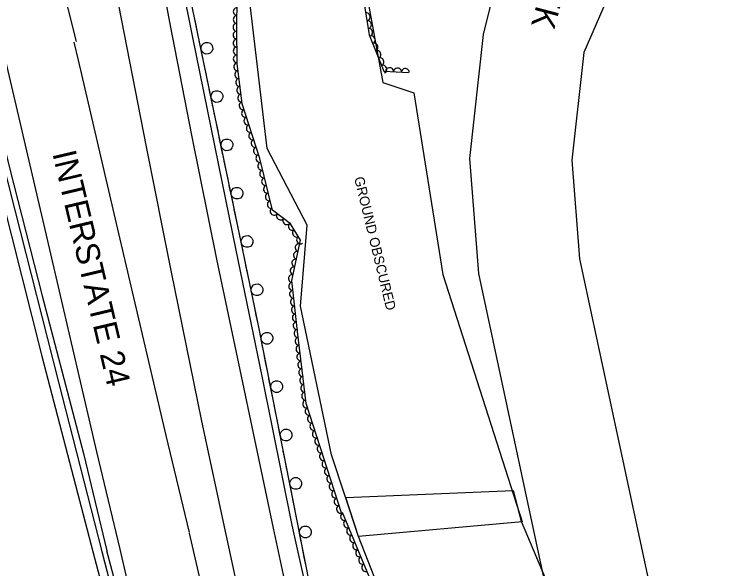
# Model space of a CAD drawing. Extents: x 1746719 to 1766531, y 631721 to 662391.
# Drawn here: x 1753932 to 1754288.6, y 651183.8 to 651464.9 of the extents above; entities that cross this region are included whole.
import ezdxf

# ---------------------------------------------------------------- set-up
doc = ezdxf.new("R2010")
doc.units = 0
for name, color, linetype in [('SURVEY - AERIAL SURVEY - Photo Control - Points - Elevations', 7, 'Continuous'), ('SURVEY - AERIAL SURVEY - Photo Control - Points - Locators', 7, 'Continuous'), ('SURVEY - AERIAL SURVEY - Photo Control - Points - Numbers', 7, 'Continuous'), ('SURVEY - AERIAL SURVEY - Photo Control with Text', 7, 'Continuous'), ('SURVEY - CONTROL - Points - Locators', 7, 'Continuous'), ('SURVEY - CONTROL - Points - Numbers', 7, 'Continuous')]:
    doc.layers.add(name, color=color, linetype=linetype)

msp = doc.modelspace()

# ---------------------------------------------------------------- linework, layer by layer
at = {"layer": 'SURVEY - AERIAL SURVEY - Photo Control - Points - Elevations'}
for points in [[(1753936.87, 651926.35), (1753944.6, 651865.12), (1753950.74, 651820.59), (1753957.41, 651772.23), (1753965.23, 651721.18), (1753973.44, 651670.2), (1753981.5, 651621.64), (1753988.03, 651583.18), (1753998.9, 651523.78), (1754010.93, 651459.97), (1754022.05, 651402.76), (1754034.51, 651340.74), (1754048.44, 651275.01), (1754063.35, 651204.56)], [(1753944.83, 651928.95), (1753952.21, 651883.69), (1753958.42, 651840.35), (1753965.12, 651789.61), (1753976.49, 651712.42), (1753982.86, 651673.43), (1753989.3, 651630.05), (1753999.61, 651567.77), (1754012.04, 651504.42), (1754022.28, 651453.88), (1754033.75, 651397.52), (1754044.29, 651345.29), (1754057.61, 651281.43), (1754072.82, 651206.04)], [(1753913.44, 651918.14), (1753925.09, 651828.85), (1753936.36, 651748.79), (1753952.06, 651651.73), (1753970.61, 651545.77), (1753983.61, 651476.45), (1753998.92, 651397.63), (1754011.4, 651335.08), (1754026.94, 651258.76), (1754039.38, 651201.31)], [(1753963.71, 651451.07), (1753955.57, 651483.26), (1753935.59, 651563.21), (1753913.95, 651648.97), (1753895.33, 651722.66), (1753876.69, 651798.75), (1753852.09, 651899.89)], [(1753816.84, 651890.61), (1753830.85, 651831.07), (1753849.61, 651754.68), (1753866.95, 651686.19), (1753887.01, 651606.61), (1753909.25, 651518.98), (1753929.48, 651433.33), (1753948.74, 651350.66), (1753973.86, 651243.1), (1753985.66, 651193.84)], [(1753794.98, 651884.53), (1753806.82, 651840.15), (1753821.01, 651784.89), (1753834.83, 651732.27), (1753860.34, 651631.97), (1753880.16, 651554.64), (1753901.48, 651468.39), (1753925.64, 651372.59), (1753946.08, 651291.56), (1753972.17, 651192.06)], [(1753962.36, 651450.73), (1753964.53, 651441.55), (1753983.8, 651358.83), (1754008.89, 651251.38), (1754020.67, 651202.22)], [(1754072.82, 651206.04), (1754094.18, 651109.83), (1754112.14, 651031.33), (1754123.49, 650982.98), (1754145.46, 650887.82), (1754164.53, 650808.3), (1754187.99, 650714.26), (1754218.11, 650592.11), (1754265.98, 650448.02)], [(1754063.35, 651204.56), (1754079.53, 651128.87), (1754096.68, 651054.56), (1754113.23, 650983.52), (1754128.08, 650921.41), (1754151.45, 650825.16), (1754182.39, 650697.84)], [(1754020.74, 651201.91), (1754034.03, 651144.22), (1754049.15, 651082.15), (1754058.18, 651048.02), (1754078.02, 650978.02), (1754103.01, 650889.26), (1754131.48, 650789.68), (1754151.45, 650719.85)], [(1754039.38, 651201.31), (1754051.19, 651146.66), (1754067.85, 651073.3), (1754085.71, 650996.02), (1754102.41, 650922.67), (1754117.55, 650859.55), (1754134.13, 650790.75), (1754151.45, 650719.85)], [(1753972.17, 651192.06), (1753992.25, 651116.01), (1754015.21, 651030.74), (1754038.02, 650948.81), (1754060.55, 650869.78), (1754089.76, 650767.41), (1754112.32, 650689.17), (1754146.8, 650566.94), (1754158.11, 650527.42), (1754160.85, 650517.83)], [(1753985.66, 651193.84), (1753999, 651135.92), (1754014.26, 651073.28), (1754023.46, 651038.51), (1754043.38, 650968.24), (1754068.37, 650879.43), (1754096.87, 650779.78), (1754126.64, 650675.65), (1754149.99, 650593.47), (1754178.2, 650495.46), (1754179.47, 650490.6)]]:
    msp.add_lwpolyline(points, dxfattribs=at)
at = {"layer": 'SURVEY - AERIAL SURVEY - Photo Control - Points - Locators'}
for points in [[(1754107.03, 651494.65), (1754118.81, 651430.22), (1754134.54, 651425.02), (1754149.25, 651333.04), (1754189.42, 651207.71), (1754106.53, 651200.34)], [(1754106.53, 651200.34), (1754092.9, 651241.67), (1754077.11, 651316.87), (1754080.55, 651357.9), (1754060.26, 651396.75), (1754051.2, 651474.09)], [(1754122.75, 651158.86), (1754106.53, 651200.34), (1754106.53, 651200.34), (1754100.19, 651220.07), (1754184.86, 651223.64), (1754189.03, 651208.12), (1754228.69, 651114.03)]]:
    msp.add_lwpolyline(points, dxfattribs=at)
at = {"layer": 'SURVEY - AERIAL SURVEY - Photo Control - Points - Numbers'}
for points in [[(1753799.94, 651885.56), (1753810.5, 651844.2), (1753821.9, 651799.8), (1753839.06, 651731.78), (1753855.62, 651667.72), (1753872.26, 651603.05), (1753890.45, 651531.05), (1753906.57, 651466.95), (1753932.35, 651365.49), (1753954.46, 651278.36), (1753976.4, 651192.62)], [(1753803.22, 651885.31), (1753820.95, 651816.44), (1753833.87, 651765.85), (1753848.12, 651709.37), (1753866.6, 651636.42), (1753879.49, 651585.73), (1753898.23, 651511.96), (1753915.25, 651443.91), (1753931.92, 651378.33), (1753946.18, 651322.21), (1753967.15, 651242.27), (1753979.08, 651193.03)], [(1754277.22, 650442.59), (1754261.86, 650465.35), (1754221.06, 650591.52), (1754167.3, 650808.68), (1754121.44, 651004.08), (1754085.73, 651156.22), (1754055.64, 651308.03), (1754019.01, 651484.3)], [(1754024.21, 651459.28), (1754023.25, 651463.88)], [(1754025.17, 651454.67), (1754024.21, 651459.28)], [(1754027.69, 651442.53), (1754025.82, 651451.54)], [(1754029.3, 651434.8), (1754028.34, 651439.4)], [(1754030.25, 651430.2), (1754029.3, 651434.8)], [(1754032.78, 651418.06), (1754030.9, 651427.06)], [(1754034.38, 651410.32), (1754033.43, 651414.92)], [(1754035.34, 651405.72), (1754034.38, 651410.32)], [(1754037.86, 651393.58), (1754035.99, 651402.59)], [(1754039.47, 651385.84), (1754038.51, 651390.45)], [(1754040.43, 651381.24), (1754039.47, 651385.84)], [(1754042.95, 651369.1), (1754041.08, 651378.11)], [(1754044.56, 651361.37), (1754043.6, 651365.97)], [(1754045.51, 651356.77), (1754044.56, 651361.37)], [(1754048.04, 651344.62), (1754046.16, 651353.63)], [(1754049.64, 651336.89), (1754048.69, 651341.49)], [(1754050.6, 651332.29), (1754049.64, 651336.89)], [(1754053.12, 651320.15), (1754051.25, 651329.16)], [(1754054.73, 651312.41), (1754053.77, 651317.01)], [(1754055.69, 651307.81), (1754055.64, 651308.03), (1754054.73, 651312.41)], [(1754058.1, 651295.65), (1754056.31, 651304.67)], [(1754059.63, 651287.9), (1754058.72, 651292.51)], [(1754060.55, 651283.29), (1754059.63, 651287.9)], [(1754062.96, 651271.12), (1754061.17, 651280.15)], [(1754064.49, 651263.38), (1754063.58, 651267.98)], [(1754065.41, 651258.77), (1754064.49, 651263.38)], [(1754067.82, 651246.6), (1754066.03, 651255.63)], [(1754069.35, 651238.85), (1754068.44, 651243.46)], [(1754070.27, 651234.24), (1754069.35, 651238.85)], [(1754072.68, 651222.08), (1754070.89, 651231.1)], [(1754074.22, 651214.33), (1754073.3, 651218.94)], [(1754075.13, 651209.72), (1754074.22, 651214.33)], [(1754077.54, 651197.56), (1754075.75, 651206.58)], [(1753976.4, 651192.62), (1753985.63, 651157.37), (1753999.56, 651107.38), (1754017.65, 651041.27), (1754039.67, 650963.99), (1754046.76, 650939.07), (1754050.77, 650921.6), (1754055, 650908.04), (1754059.02, 650896.07), (1754079.37, 650824.52), (1754099.29, 650754.42), (1754120.26, 650679.29), (1754139.53, 650612.32), (1754166.51, 650517.9)], [(1754175.8, 650492.56), (1754160.24, 650546.46), (1754142.04, 650609.69), (1754125.24, 650668.34), (1754110.86, 650720.6), (1754096.24, 650772.39), (1754077.82, 650836.36), (1754059.64, 650900.45), (1754056.28, 650915.36), (1754049.84, 650936.52), (1754045.21, 650951.78), (1754029.02, 651009.31), (1754011.97, 651069.98), (1753996.6, 651127.12), (1753979.08, 651193.03)], [(1754079.08, 651189.81), (1754078.16, 651194.42)], [(1754079.99, 651185.2), (1754079.08, 651189.81)]]:
    msp.add_lwpolyline(points, dxfattribs=at)
for centre, start, end in [((1754029.7, 651447.6), 305.0086, 304.9946), ((1754034.79, 651423.13), 305.0086, 304.9946), ((1754039.87, 651398.65), 305.0086, 304.9946), ((1754044.96, 651374.17), 305.0086, 304.9946), ((1754050.05, 651349.69), 305.0086, 304.9946), ((1754055.13, 651325.22), 305.0086, 304.9946), ((1754060.15, 651300.7), 304.4806, 304.4666), ((1754065.01, 651276.18), 304.4806, 304.4666), ((1754069.87, 651251.65), 304.4806, 304.4666), ((1754074.74, 651227.13), 304.4806, 304.4666), ((1754079.6, 651202.61), 304.4806, 304.4666)]:
    msp.add_arc(centre, 3, start, end, dxfattribs=at)
at = {"layer": 'SURVEY - AERIAL SURVEY - Photo Control with Text'}
for points in [[(1754123.93, 651635.81), (1754115.82, 651605.86), (1754110.63, 651577), (1754119.1, 651558.62), (1754109.82, 651530.12), (1754111.19, 651508.9), (1754112.78, 651492.66), (1754113.58, 651478.66), (1754109.82, 651468.02), (1754111.99, 651454.45), (1754119.32, 651436.02), (1754131.93, 651435.29)], [(1754097.88, 651212.2), (1754080.09, 651267.57), (1754075.68, 651304.12), (1754072.73, 651329.92), (1754077.14, 651350.37), (1754072.11, 651358.68), (1754062.94, 651365.54), (1754056.47, 651391.66), (1754047.65, 651419.45), (1754044.97, 651439.9), (1754044.89, 651457.95), (1754045.24, 651487.87)], [(1754437.51, 650352.91), (1754373.46, 650364.73), (1754342.18, 650371.08), (1754330.7, 650387.52), (1754322.19, 650421.14), (1754324.94, 650470.68), (1754320.13, 650524.69), (1754316.48, 650564.69), (1754305.81, 650600.41), (1754286.82, 650634.23), (1754280.52, 650686.12), (1754274.54, 650724.16), (1754269.28, 650750.14), (1754249.03, 650765.51), (1754227.91, 650772.31), (1754210.67, 650824.74), (1754196.82, 650877.62), (1754188.5, 650922.64), (1754171.01, 650976.43), (1754157.32, 651016.92), (1754145.6, 651062.07), (1754133.69, 651111.97), (1754119.69, 651161.21), (1754098.48, 651212.49)]]:
    msp.add_lwpolyline(points, dxfattribs=at)
for centre, major_axis in [((1754044.98, 651466.18), (0.02, 2)), ((1754044.94, 651462.18), (0.02, 2)), ((1754110.54, 651463.52), (0.32, -1.97)), ((1754044.89, 651458.18), (0.02, 2)), ((1754111.17, 651459.57), (0.32, -1.97)), ((1754044.9, 651454.18), (-0.01, 2)), ((1754111.81, 651455.62), (0.32, -1.97)), ((1754044.92, 651450.18), (-0.01, 2)), ((1754113.03, 651451.83), (0.74, -1.86)), ((1754114.51, 651448.12), (0.74, -1.86)), ((1754044.94, 651446.18), (-0.01, 2)), ((1754115.99, 651444.4), (0.74, -1.86)), ((1754044.96, 651442.18), (-0.01, 2)), ((1754117.47, 651440.68), (0.74, -1.86)), ((1754045.19, 651438.19), (-0.26, 1.98)), ((1754118.95, 651436.97), (0.74, -1.86)), ((1754122.3, 651435.85), (2, -0.12)), ((1754045.71, 651434.23), (-0.26, 1.98)), ((1754126.29, 651435.62), (2, -0.12)), ((1754130.28, 651435.39), (2, -0.12)), ((1754046.23, 651430.26), (-0.26, 1.98)), ((1754046.76, 651426.3), (-0.26, 1.98)), ((1754047.28, 651422.33), (-0.26, 1.98)), ((1754047.98, 651418.41), (-0.6, 1.91)), ((1754049.19, 651414.59), (-0.6, 1.91)), ((1754050.4, 651410.78), (-0.6, 1.91)), ((1754051.61, 651406.97), (-0.6, 1.91)), ((1754052.82, 651403.16), (-0.6, 1.91)), ((1754054.03, 651399.34), (-0.6, 1.91)), ((1754055.24, 651395.53), (-0.6, 1.91)), ((1754056.45, 651391.72), (-0.6, 1.91)), ((1754057.42, 651387.84), (-0.48, 1.94)), ((1754058.38, 651383.95), (-0.48, 1.94)), ((1754059.34, 651380.07), (-0.48, 1.94)), ((1754060.3, 651376.19), (-0.48, 1.94)), ((1754061.26, 651372.31), (-0.48, 1.94)), ((1754062.23, 651368.42), (-0.48, 1.94)), ((1754063.77, 651364.92), (-1.6, 1.2)), ((1754066.97, 651362.53), (-1.6, 1.2)), ((1754070.17, 651360.13), (-1.6, 1.2)), ((1754072.93, 651357.33), (-1.04, 1.71)), ((1754075, 651353.91), (-1.04, 1.71)), ((1754077.07, 651350.49), (-1.04, 1.71)), ((1754076.33, 651346.59), (0.42, 1.95)), ((1754075.48, 651342.68), (0.42, 1.95)), ((1754074.64, 651338.77), (0.42, 1.95)), ((1754073.79, 651334.86), (0.42, 1.95)), ((1754072.95, 651330.95), (0.42, 1.95)), ((1754073.06, 651327), (-0.23, 1.99)), ((1754073.51, 651323.02), (-0.23, 1.99)), ((1754073.97, 651319.05), (-0.23, 1.99)), ((1754074.42, 651315.07), (-0.23, 1.99)), ((1754074.88, 651311.1), (-0.23, 1.99)), ((1754075.33, 651307.12), (-0.23, 1.99)), ((1754075.79, 651303.15), (-0.24, 1.99)), ((1754076.27, 651299.18), (-0.24, 1.99)), ((1754076.75, 651295.21), (-0.24, 1.99)), ((1754077.23, 651291.24), (-0.24, 1.99)), ((1754077.71, 651287.27), (-0.24, 1.99)), ((1754078.19, 651283.3), (-0.24, 1.99)), ((1754078.67, 651279.32), (-0.24, 1.99)), ((1754079.15, 651275.35), (-0.24, 1.99)), ((1754079.63, 651271.38), (-0.24, 1.99)), ((1754080.14, 651267.42), (-0.61, 1.9)), ((1754081.36, 651263.61), (-0.61, 1.9)), ((1754082.58, 651259.8), (-0.61, 1.9)), ((1754083.81, 651255.99), (-0.61, 1.9)), ((1754085.03, 651252.18), (-0.61, 1.9)), ((1754086.25, 651248.38), (-0.61, 1.9)), ((1754087.48, 651244.57), (-0.61, 1.9)), ((1754088.7, 651240.76), (-0.61, 1.9)), ((1754089.93, 651236.95), (-0.61, 1.9)), ((1754091.15, 651233.14), (-0.61, 1.9)), ((1754092.37, 651229.34), (-0.61, 1.9)), ((1754093.6, 651225.53), (-0.61, 1.9)), ((1754094.82, 651221.72), (-0.61, 1.9)), ((1754096.05, 651217.91), (-0.61, 1.9)), ((1754097.27, 651214.1), (-0.61, 1.9)), ((1754099.37, 651210.35), (-0.76, 1.85)), ((1754100.89, 651206.66), (-0.76, 1.85)), ((1754102.42, 651202.96), (-0.76, 1.85)), ((1754103.95, 651199.26), (-0.76, 1.85)), ((1754105.48, 651195.57), (-0.76, 1.85)), ((1754107.01, 651191.87), (-0.76, 1.85)), ((1754108.54, 651188.17), (-0.76, 1.85)), ((1754110.06, 651184.48), (-0.76, 1.85))]:
    msp.add_ellipse(centre, major_axis=major_axis, ratio=0.940188, start_param=0, end_param=3.141593, dxfattribs=at)
at = {"layer": 'SURVEY - CONTROL - Points - Locators'}
for points in [[(1754355.39, 651800.12), (1754279.49, 651732.05), (1754250.7, 651685.75), (1754218.54, 651615.28), (1754190.08, 651536.67), (1754169.64, 651454.54), (1754162.69, 651391.74), (1754167.28, 651333.43), (1754239.48, 650996.5), (1754258.15, 650928.17), (1754277.98, 650866.22), (1754308.69, 650819.4), (1754334.91, 650784.12), (1754384.39, 650741.68), (1754438.42, 650718.28), (1754518.34, 650691.93), (1754607.58, 650664.15), (1754710.2, 650648.48)], [(1754389.89, 651761.65), (1754319.48, 651698.5), (1754296.33, 651661.28), (1754262.05, 651598.43), (1754247.41, 651506.85), (1754220.62, 651445.41), (1754214.59, 651390.92), (1754218.53, 651340.91), (1754289.71, 651008.73), (1754307.7, 650942.87), (1754325.06, 650888.68), (1754351.07, 650849.01), (1754367.14, 650811.09), (1754406.29, 650777.49), (1754456.82, 650766.63), (1754530.29, 650748.7), (1754619.23, 650714.65), (1754717.99, 650699.57)]]:
    msp.add_lwpolyline(points, dxfattribs=at)

# ---------------------------------------------------------------- texts
at = {"layer": 'SURVEY - AERIAL SURVEY - Photo Control - Points - Locators'}
msp.add_text('GROUND OBSCURED', height=5, rotation=283.7394, dxfattribs=at).set_placement((1754104.27, 651381.86))
at = {"layer": 'SURVEY - CONTROL - Points - Numbers'}
for s, rotation, p in [('MILL CREEK', 255.277, (1754218.18, 651551.59)), ('INTERSTATE 24', 283.2904, (1753951.37, 651394.34))]:
    msp.add_text(s, height=12, rotation=rotation, dxfattribs=at).set_placement(p)

doc.saveas('drawing.dxf')
